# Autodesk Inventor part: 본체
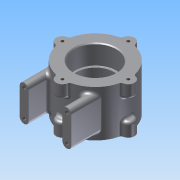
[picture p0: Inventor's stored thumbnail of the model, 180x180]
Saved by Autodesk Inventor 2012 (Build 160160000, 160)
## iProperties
Created: 2007-01
Part Number: 본체
Material: Default
Document SubType Name: Modeling
Designer: net
Density: 1 g/cm^3
Author: net
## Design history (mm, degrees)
sketch "스케치1"
  geometry: C1 r 37 at (0, 0); 1 further point
  constraints: 1 centre point, 1 coincident
  dimensions: "d0" = 74 diameter of C1
extrude "돌출1" new body sketch "스케치1" distance "d1" = 52; taper "d2" = 0 deg
node "작업 평면2"
sketch "스케치3"
  geometry: L1 (-37, 0)-(-37, 52) reference; L2 (37, 0)-(37, 52) reference; L3 (-29, 41)-(-29, 11); L4 (-29, 11)-(-29, 41); L5 (-19, 11)-(-19, 41); L6 (19, 11)-(19, 41); L7 (29, 41)-(29, 11); L8 (-19, 26)-(19, 26); A1 r 5 centre (-24, 11) between (-29, 11) and (-19, 11); A2 r 5 centre (-24, 41) between (-19, 41) and (-29, 41); A3 r 5 centre (24, 41) between (29, 41) and (19, 41); A4 r 5 centre (24, 11) between (19, 11) and (29, 11); 3 further points
  constraints: 13 end point, 8 point on circle, 8 tangent, 5 parallel, 4 centre point, 4 midpoint, 1 equal radius, 1 horizontal, 1 horizontal alignment, 1 vertical alignment
  dimensions: "d5" = 48 distance of A4.centre A1.centre; "d7" = 10 distance between parallel lines of L6 L7; "d153" = 40 dimension on A4 A3
extrude "돌출2" join sketch "스케치3" distance "d9" = 56; taper "d10" = 0 deg
sketch "스케치4"
  geometry: C1 r 7 at (0, 37); 1 further point
  constraints: 2 vertical alignment, 1 centre point, 1 other
  dimensions: "d11" = 14 diameter of C1
extrude "돌출3" join sketch "스케치4" distance "d12" = 15; taper "d13" = 0 deg
sketch "스케치5"
  geometry: C1 r 7 at (0, 37); A1 r 37 centre (0, 0) between (6.969, 36.338) and (-6.969, 36.338) reference; A2 r 7 centre (0, 37) between (6.969, 36.338) and (-6.969, 36.338) reference
  constraints: 1 centre point, 1 coincident
  dimensions: "d17" = 14 diameter of C1
extrude "돌출4" join sketch "스케치5" distance "d18" = 15; taper "d19" = 0 deg
sketch "스케치6"
  geometry: C1 r 23.5 at (0, 0); A1 r 37 centre (0, 0) between (6.969, -36.338) and (36.338, -6.969) reference
  constraints: 1 centre point, 1 coincident
  dimensions: "d23" = 47 diameter of C1
extrude "돌출5" cut sketch "스케치6" distance "d24" = 22; taper "d25" = 0 deg
sketch "스케치7"
  geometry: C1 r 23.5 at (0, 0); A1 r 37 centre (0, 0) between (36.338, 6.969) and (6.969, 36.338) reference
  constraints: 1 centre point, 1 coincident
  dimensions: "d26" = 47 diameter of C1
extrude "돌출6" cut sketch "스케치7" distance "d27" = 22; taper "d28" = 0 deg
sketch "스케치8"
  geometry: C1 r 23.5 at (0, 0) reference; C2 r 21 at (0, 0)
  constraints: 1 centre point, 1 coincident
  dimensions: "d29" = 42 diameter of C2
extrude "돌출7" cut sketch "스케치8" stored distance "d30" = 22; taper "d31" = 0 deg
hole "구멍1" diameter "d34" = 3.242; stored, may be unused: countersink angle "d38" = 90 deg, drill point angle "d40" = 118 deg; dims "d32" = 10, "d33" = 10, "d35" = 8, "d36" = 4, "d37" = 2, "d39" = 11
hole "구멍2" diameter "d43" = 3.242; stored, may be unused: countersink angle "d47" = 90 deg, drill point angle "d49" = 118 deg; dims "d41" = 10, "d42" = 10, "d44" = 8, "d45" = 4, "d46" = 2, "d48" = 11
hole "구멍3" diameter "d52" = 3.242; stored, may be unused: countersink angle "d56" = 90 deg, drill point angle "d58" = 118 deg; dims "d50" = 10, "d51" = 10, "d53" = 8, "d54" = 4, "d55" = 2, "d57" = 11
hole "구멍4" diameter "d61" = 3.242; stored, may be unused: countersink angle "d65" = 90 deg, drill point angle "d67" = 118 deg; dims "d59" = 10, "d60" = 10, "d62" = 8, "d63" = 4, "d64" = 2, "d66" = 11
hole "구멍5" diameter "d70" = 3.242; stored, may be unused: countersink angle "d74" = 90 deg, drill point angle "d76" = 118 deg; dims "d68" = 10, "d69" = 10, "d71" = 8, "d72" = 4, "d73" = 2, "d75" = 11
hole "구멍6" diameter "d79" = 3.242; stored, may be unused: countersink angle "d83" = 90 deg, drill point angle "d85" = 118 deg; dims "d77" = 10, "d78" = 10, "d80" = 8, "d81" = 4, "d82" = 2, "d84" = 11
hole "구멍7" diameter "d88" = 3.242; stored, may be unused: countersink angle "d92" = 90 deg, drill point angle "d94" = 118 deg; dims "d86" = 10, "d87" = 10, "d89" = 8, "d90" = 4, "d91" = 2, "d93" = 11
hole "구멍8" diameter "d97" = 3.242; stored, may be unused: countersink angle "d101" = 90 deg, drill point angle "d103" = 118 deg; dims "d95" = 10, "d96" = 10, "d98" = 8, "d99" = 4, "d100" = 2, "d102" = 11
hole "구멍9" diameter "d106" = 4.134; stored, may be unused: countersink angle "d110" = 90 deg, drill point angle "d112" = 118 deg; dims "d104" = 10, "d105" = 10, "d107" = 6, "d108" = 4, "d109" = 2, "d111" = 8
hole "구멍10" diameter "d115" = 4.134; stored, may be unused: countersink angle "d119" = 90 deg, drill point angle "d121" = 118 deg; dims "d113" = 10, "d114" = 10, "d116" = 6, "d117" = 4, "d118" = 2, "d120" = 8
hole "구멍11" diameter "d124" = 4.134; stored, may be unused: countersink angle "d128" = 90 deg, drill point angle "d130" = 118 deg; dims "d122" = 10, "d123" = 10, "d125" = 6, "d126" = 4, "d127" = 2, "d129" = 8
hole "구멍12" diameter "d133" = 4.134; stored, may be unused: countersink angle "d137" = 90 deg, drill point angle "d139" = 118 deg; dims "d131" = 10, "d132" = 10, "d134" = 6, "d135" = 4, "d136" = 2, "d138" = 8
node "작업 평면3"
sketch "스케치9"
  geometry: L1 (29, -22.978)-(29, -56) reference; L2 (29, -56)-(19, -56) reference; L3 (19, -56)-(19, -31.749) reference; L4 (-19, -31.749)-(-19, -56) reference; L5 (-19, -56)-(-29, -56) reference; L6 (-29, -56)-(-29, -22.978) reference; L7 (0, 0)-(26.163, 26.163); L8 (0, 0)-(37, 0); C1 r 21 at (0, 0) reference; A1 r 37 centre (0, 0) between (29, -22.978) and (-29, -22.978) reference; A2 r 37 centre (0, 0) between (-19, -31.749) and (19, -31.749) reference; 1 further point
  constraints: 4 end point, 2 point on circle, 1 perpendicular
  dimensions: "d141" = 45 deg angle of L8 L7
  node "절단 모서리 투영1"
node "작업 평면4"
fillet "모깎기1" dims "d146" = 3
fillet "모깎기2" dims "d147" = 3
fillet "모깎기3" dims "d148" = 3
fillet "모깎기4" dims "d149" = 0.3
chamfer "모따기1" distance "d150" = 1; stored, may be unused: second distance "d151" = 2, angle "d152" = 45 deg
sketch "스케치11"
  geometry: L1 (-18.921, -26)-(18.921, -26) reference; 2 further points
  constraints: 1 other
  dimensions: "d154" = 26 distance from line of L1 point (0, 0); "d155" = 0 horizontal distance of point (0, -26) point (0, 0)
feature "엠보싱2" sketch "스케치11" dims "d0" = 74, "d156" = 0.5, "d157" = 0
node "솔리드1"
pattern_circular "원형 패턴1" dims angle "d15" = 360 deg
pattern_circular "원형 패턴2" dims angle "d21" = 360 deg
node "투영된 루프1"
other parameters: "d4" = -56, "d140" = 26
